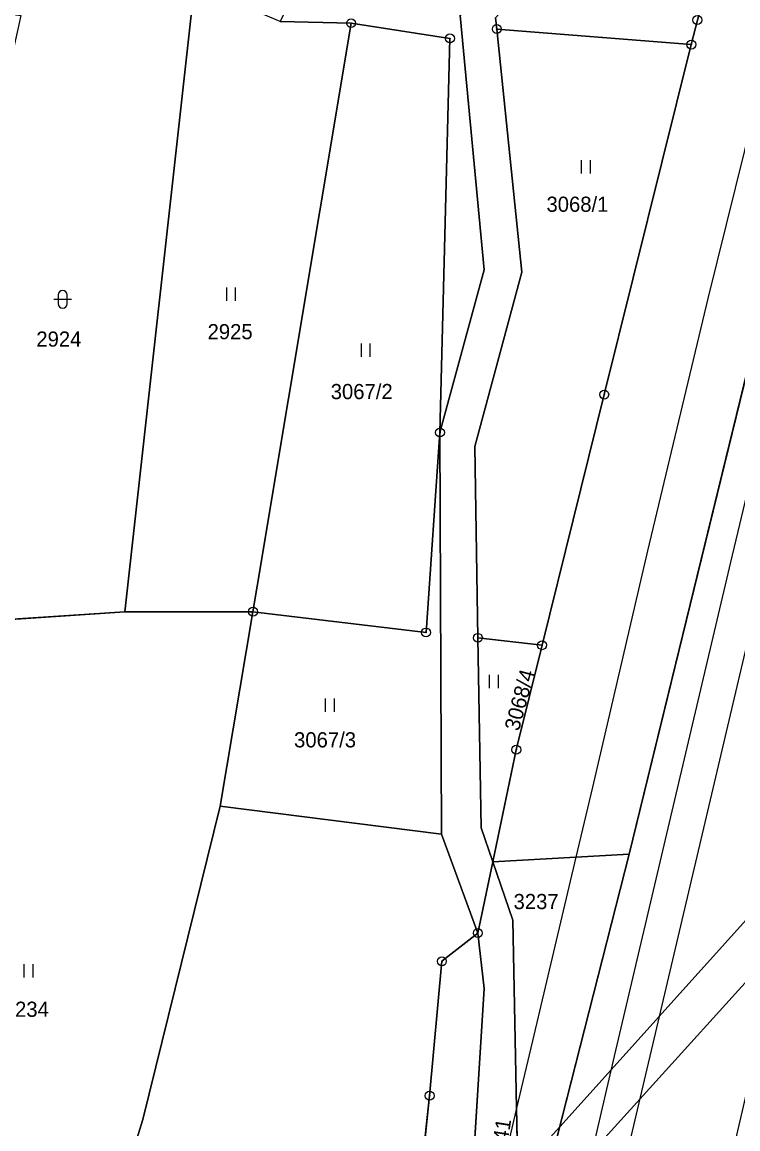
# Model space of a CAD drawing. Extents: x -689422 to -685210, y -987725 to -982160.
# Drawn here: x -686926.7 to -686846.4, y -987064.7 to -986940.6 of the extents above; entities that cross this region are included whole.
import ezdxf

# ---------------------------------------------------------------- set-up
doc = ezdxf.new("R2010")
doc.units = 0
for name, color, linetype in [('KN_Hranice_parcel', 7, 'Continuous'), ('KN_Hranice_parcel_vnitrni_kresba', 7, 'Continuous'), ('KN_Parcelni cisla', 7, 'Continuous'), ('KN_Polygon parcely', 7, 'Continuous'), ('KN_POZEMKY_OSTATNI PLOCHA', 7, 'Continuous'), ('KN_POZEMKY_TTP', 7, 'Continuous'), ('KN_POZEMKY_VODNI_PLOCHA', 7, 'Continuous'), ('KN_VYUZITI_11_vodni plocha_zamokrena plocha', 7, 'Continuous'), ('KN_VYUZITI_16_ostatni plocha_silnice', 7, 'Continuous'), ('KN_VYUZITI_27_ostatni plocha_neplodna puda', 7, 'Continuous'), ('KN_Věcná břemena k části', 7, 'Continuous'), ('KN_Značky bodu BP', 7, 'Continuous'), ('KN_Značky kultur', 7, 'Continuous')]:
    doc.layers.add(name, color=color, linetype=linetype)

msp = doc.modelspace()

# ---------------------------------------------------------------- linework, layer by layer
at = {"layer": 'KN_Hranice_parcel'}
for p, q in [((-686915.21, -987006.73), (-686907.58, -986938.09)), ((-686900.35, -987003.88), (-686889.82, -986940.72)), ((-686889.82, -986940.72), (-686897.78, -986940.52)), ((-686873.61, -986940.12), (-686873.48, -986941.38)), ((-686850.98, -986940.37), (-686851.66, -986943.12)), ((-686851.66, -986943.12), (-686873.48, -986941.38)), ((-686873.48, -986941.38), (-686870.67, -986968.64)), ((-686870.67, -986968.64), (-686875.95, -986988.19)), ((-686879.67, -987031.69), (-686879.86, -986986.63)), ((-686875.95, -986988.19), (-686875.6, -987009.66)), ((-686900.83, -987006.73), (-686900.35, -987003.88)), ((-686941.32, -987008.49), (-686915.21, -987006.73)), ((-686915.21, -987006.73), (-686900.83, -987006.73)), ((-686904.51, -987028.55), (-686900.83, -987006.73)), ((-686875.6, -987009.66), (-686875.25, -987030.98)), ((-686875.6, -987009.66), (-686868.4, -987010.49)), ((-686868.4, -987010.49), (-686871.3, -987022.21)), ((-686871.3, -987022.21), (-686873.93, -987034.78)), ((-686904.51, -987028.55), (-686879.67, -987031.69)), ((-686875.25, -987030.98), (-686873.93, -987034.78)), ((-686879.67, -987031.69), (-686875.61, -987042.77)), ((-686858.63, -987033.94), (-686876.05, -987102.29)), ((-686873.93, -987034.78), (-686875.61, -987042.77)), ((-686873.93, -987034.78), (-686871.67, -987041.32)), ((-686874.91, -987049.01), (-686875.61, -987042.77))]:
    msp.add_line(p, q, dxfattribs=at)
for points in [[(-686809.37, -986846.02), (-686821.44, -986885.64), (-686838.14, -986950.08), (-686858.63, -987033.94)], [(-686879.86, -986986.63), (-686874.89, -986968.38), (-686877.6, -986939.87), (-686859.95, -986918.72), (-686851.59, -986903.08), (-686841, -986883.31)], [(-686889.82, -986940.72), (-686878.74, -986942.43), (-686879.86, -986986.63)], [(-686851.66, -986943.12), (-686861.43, -986982.38), (-686868.4, -987010.49)], [(-686900.83, -987006.73), (-686881.42, -987009.06), (-686879.86, -986986.63)], [(-686926.56, -987106.84), (-686913.19, -987063.68), (-686904.51, -987028.55)], [(-686873.93, -987034.78), (-686864.62, -987034.27), (-686858.63, -987033.94)], [(-686871.67, -987041.32), (-686871.26, -987062.4), (-686871.04, -987073.57), (-686876.05, -987102.29)], [(-686875.61, -987042.77), (-686879.64, -987045.94), (-686881.02, -987061.02), (-686881.88, -987069.03), (-686889.8, -987097.99), (-686895.85, -987125.85)], [(-686876.05, -987102.29), (-686879.24, -987096.41), (-686879.53, -987095.87), (-686876.38, -987072.98), (-686874.91, -987049.01)]]:
    msp.add_lwpolyline(points, dxfattribs=at)
at = {"layer": 'KN_Hranice_parcel_vnitrni_kresba'}
for p, q in [((-686842.22, -986940.88), (-686849.82, -986971.61)), ((-686875.39, -987137.96), (-686832.86, -986956.93)), ((-686849.82, -986971.61), (-686856.59, -986999.9)), ((-686840.72, -986973.62), (-686847.25, -987001.16)), ((-686856.59, -986999.9), (-686862.76, -987026.4)), ((-686847.25, -987001.16), (-686853.68, -987028.46)), ((-686862.76, -987026.4), (-686864.62, -987034.27)), ((-686853.68, -987028.46), (-686860.31, -987056.58)), ((-686864.62, -987034.27), (-686869.48, -987054.85)), ((-686839.49, -987034.76), (-686861.96, -987131.65)), ((-686869.48, -987054.85), (-686871.26, -987062.4)), ((-686860.31, -987056.58), (-686866.54, -987083.15)), ((-686871.26, -987062.4), (-686875.64, -987081.01))]:
    msp.add_line(p, q, dxfattribs=at)
at = {"layer": 'KN_Polygon parcely'}
msp.add_lwpolyline([(-686747.09, -986687.93), (-686785.68, -986782.79), (-686794.86, -986807.28), (-686809.37, -986846.02), (-686821.44, -986885.64), (-686838.14, -986950.08), (-686858.63, -987033.94), (-686876.05, -987102.29)], dxfattribs=at)
for points in [[(-686815.24, -986827.16), (-686821.42, -986841.08), (-686827.34, -986859.08), (-686829.67, -986866.16), (-686840.54, -986901.19), (-686850.98, -986940.37), (-686851.66, -986943.12), (-686861.43, -986982.38), (-686868.4, -987010.49), (-686871.3, -987022.21), (-686873.93, -987034.78), (-686864.62, -987034.27), (-686858.63, -987033.94), (-686838.14, -986950.08), (-686821.44, -986885.64), (-686809.37, -986846.02), (-686794.86, -986807.28), (-686798.92, -986805.5), (-686805.65, -986802.54), (-686814.47, -986825.93), (-686813.96, -986826.56)], [(-686875.61, -987042.77), (-686873.93, -987034.78), (-686875.25, -987030.98), (-686875.6, -987009.66), (-686875.95, -986988.19), (-686870.67, -986968.64), (-686873.48, -986941.38), (-686873.61, -986940.12), (-686856.81, -986921.45), (-686848.29, -986905.16), (-686836.78, -986883.92), (-686840.43, -986873.61), (-686835.56, -986856.29), (-686839.5, -986854.96), (-686846.18, -986872.83), (-686841, -986883.31), (-686851.59, -986903.08), (-686859.95, -986918.72), (-686877.6, -986939.87), (-686874.89, -986968.38), (-686879.86, -986986.63), (-686879.67, -987031.69)], [(-686840.43, -986873.61), (-686836.78, -986883.92), (-686848.29, -986905.16), (-686856.81, -986921.45), (-686873.61, -986940.12), (-686873.48, -986941.38), (-686851.66, -986943.12), (-686850.98, -986940.37), (-686840.54, -986901.19), (-686829.67, -986866.16), (-686827.34, -986859.08), (-686835.56, -986856.29)], [(-686859.95, -986918.72), (-686851.59, -986903.08), (-686841, -986883.31), (-686861.16, -986874.49), (-686878.99, -986900.95), (-686897.78, -986940.52), (-686889.82, -986940.72), (-686878.74, -986942.43), (-686879.86, -986986.63), (-686874.89, -986968.38), (-686877.6, -986939.87)], [(-686941.32, -987008.49), (-686915.21, -987006.73), (-686907.58, -986938.09), (-686916.04, -986936.88), (-686931.42, -986936.56), (-687035.22, -986921.09), (-687034.96, -986923.61), (-686936.47, -986938.56), (-686926.88, -986939.87), (-686941.35, -987005.33), (-686948.57, -987004.84), (-686981.97, -987002.56), (-687034.11, -986992.05), (-687034.08, -986994.23), (-686980.97, -987004.74)], [(-686900.83, -987006.73), (-686900.35, -987003.88), (-686889.82, -986940.72), (-686897.78, -986940.52), (-686901.51, -986938.95), (-686907.58, -986938.09), (-686915.21, -987006.73)], [(-686879.86, -986986.63), (-686878.74, -986942.43), (-686889.82, -986940.72), (-686900.35, -987003.88), (-686900.83, -987006.73), (-686881.42, -987009.06)], [(-686873.48, -986941.38), (-686870.67, -986968.64), (-686875.95, -986988.19), (-686875.6, -987009.66), (-686868.4, -987010.49), (-686861.43, -986982.38), (-686851.66, -986943.12)], [(-686879.67, -987031.69), (-686879.86, -986986.63), (-686881.42, -987009.06), (-686900.83, -987006.73), (-686904.51, -987028.55)], [(-686904.51, -987028.55), (-686900.83, -987006.73), (-686915.21, -987006.73), (-686941.32, -987008.49), (-686941.23, -987025.06), (-686947.38, -987090.16), (-686929.71, -987120.98), (-686926.56, -987106.84), (-686913.19, -987063.68)], [(-686873.93, -987034.78), (-686871.3, -987022.21), (-686868.4, -987010.49), (-686875.6, -987009.66), (-686875.25, -987030.98)], [(-686926.56, -987106.84), (-686895.85, -987125.85), (-686889.8, -987097.99), (-686881.88, -987069.03), (-686881.02, -987061.02), (-686879.64, -987045.94), (-686875.61, -987042.77), (-686879.67, -987031.69), (-686904.51, -987028.55), (-686913.19, -987063.68)], [(-686871.04, -987073.57), (-686876.05, -987102.29), (-686858.63, -987033.94), (-686864.62, -987034.27), (-686873.93, -987034.78), (-686871.67, -987041.32), (-686871.26, -987062.4)], [(-686875.61, -987042.77), (-686874.91, -987049.01), (-686876.38, -987072.98), (-686879.53, -987095.87), (-686879.24, -987096.41), (-686876.05, -987102.29), (-686871.04, -987073.57), (-686871.26, -987062.4), (-686871.67, -987041.32), (-686873.93, -987034.78)], [(-686895.85, -987125.85), (-686887.4, -987131.07), (-686882.17, -987134.31), (-686880.68, -987119.19), (-686879.29, -987115), (-686876.05, -987102.29), (-686879.24, -987096.41), (-686879.53, -987095.87), (-686876.38, -987072.98), (-686874.91, -987049.01), (-686875.61, -987042.77), (-686879.64, -987045.94), (-686881.02, -987061.02), (-686881.88, -987069.03), (-686889.8, -987097.99)]]:
    msp.add_lwpolyline(points, close=True, dxfattribs=at)
at = {"layer": 'KN_POZEMKY_OSTATNI PLOCHA'}
for p, q in [((-686907.58, -986938.09), (-686915.21, -987006.73)), ((-686851.66, -986943.12), (-686850.98, -986940.37)), ((-686861.43, -986982.38), (-686851.66, -986943.12)), ((-686838.14, -986950.08), (-686858.63, -987033.94)), ((-686858.63, -987033.94), (-686838.14, -986950.08)), ((-686868.4, -987010.49), (-686861.43, -986982.38)), ((-686915.21, -987006.73), (-686941.32, -987008.49)), ((-686871.3, -987022.21), (-686868.4, -987010.49)), ((-686873.93, -987034.78), (-686871.3, -987022.21)), ((-686876.05, -987102.29), (-686858.63, -987033.94)), ((-686858.63, -987033.94), (-686876.05, -987102.29)), ((-686858.63, -987033.94), (-686864.62, -987034.27)), ((-686864.62, -987034.27), (-686858.63, -987033.94)), ((-686875.61, -987042.77), (-686873.93, -987034.78)), ((-686864.62, -987034.27), (-686873.93, -987034.78)), ((-686873.93, -987034.78), (-686864.62, -987034.27)), ((-686871.67, -987041.32), (-686873.93, -987034.78)), ((-686873.93, -987034.78), (-686871.67, -987041.32)), ((-686871.26, -987062.4), (-686871.67, -987041.32)), ((-686871.67, -987041.32), (-686871.26, -987062.4)), ((-686879.64, -987045.94), (-686875.61, -987042.77)), ((-686874.91, -987049.01), (-686875.61, -987042.77)), ((-686875.61, -987042.77), (-686874.91, -987049.01)), ((-686881.02, -987061.02), (-686879.64, -987045.94)), ((-686876.38, -987072.98), (-686874.91, -987049.01)), ((-686874.91, -987049.01), (-686876.38, -987072.98)), ((-686881.88, -987069.03), (-686881.02, -987061.02)), ((-686871.04, -987073.57), (-686871.26, -987062.4)), ((-686871.26, -987062.4), (-686871.04, -987073.57))]:
    msp.add_line(p, q, dxfattribs=at)
at = {"layer": 'KN_POZEMKY_TTP'}
for p, q in [((-686915.21, -987006.73), (-686907.58, -986938.09)), ((-686889.82, -986940.72), (-686900.35, -987003.88)), ((-686900.35, -987003.88), (-686889.82, -986940.72)), ((-686897.78, -986940.52), (-686889.82, -986940.72)), ((-686889.82, -986940.72), (-686897.78, -986940.52)), ((-686878.74, -986942.43), (-686889.82, -986940.72)), ((-686889.82, -986940.72), (-686878.74, -986942.43)), ((-686877.6, -986939.87), (-686874.89, -986968.38)), ((-686873.48, -986941.38), (-686873.61, -986940.12)), ((-686850.98, -986940.37), (-686851.66, -986943.12)), ((-686870.67, -986968.64), (-686873.48, -986941.38)), ((-686873.48, -986941.38), (-686851.66, -986943.12)), ((-686851.66, -986943.12), (-686873.48, -986941.38)), ((-686879.86, -986986.63), (-686878.74, -986942.43)), ((-686878.74, -986942.43), (-686879.86, -986986.63)), ((-686851.66, -986943.12), (-686861.43, -986982.38)), ((-686874.89, -986968.38), (-686879.86, -986986.63)), ((-686875.95, -986988.19), (-686870.67, -986968.64)), ((-686861.43, -986982.38), (-686868.4, -987010.49)), ((-686879.86, -986986.63), (-686881.42, -987009.06)), ((-686881.42, -987009.06), (-686879.86, -986986.63)), ((-686879.86, -986986.63), (-686879.67, -987031.69)), ((-686875.6, -987009.66), (-686875.95, -986988.19)), ((-686900.35, -987003.88), (-686900.83, -987006.73)), ((-686900.83, -987006.73), (-686900.35, -987003.88)), ((-686941.32, -987008.49), (-686915.21, -987006.73)), ((-686900.83, -987006.73), (-686915.21, -987006.73)), ((-686915.21, -987006.73), (-686900.83, -987006.73)), ((-686900.83, -987006.73), (-686904.51, -987028.55)), ((-686904.51, -987028.55), (-686900.83, -987006.73)), ((-686881.42, -987009.06), (-686900.83, -987006.73)), ((-686900.83, -987006.73), (-686881.42, -987009.06)), ((-686868.4, -987010.49), (-686875.6, -987009.66)), ((-686875.6, -987009.66), (-686868.4, -987010.49)), ((-686875.25, -987030.98), (-686875.6, -987009.66)), ((-686868.4, -987010.49), (-686871.3, -987022.21)), ((-686871.3, -987022.21), (-686873.93, -987034.78)), ((-686904.51, -987028.55), (-686913.19, -987063.68)), ((-686913.19, -987063.68), (-686904.51, -987028.55)), ((-686904.51, -987028.55), (-686879.67, -987031.69)), ((-686879.67, -987031.69), (-686904.51, -987028.55)), ((-686873.93, -987034.78), (-686875.25, -987030.98)), ((-686879.67, -987031.69), (-686875.61, -987042.77)), ((-686875.61, -987042.77), (-686879.64, -987045.94)), ((-686879.64, -987045.94), (-686881.02, -987061.02)), ((-686881.02, -987061.02), (-686881.88, -987069.03)), ((-686913.19, -987063.68), (-686926.56, -987106.84)), ((-686926.56, -987106.84), (-686913.19, -987063.68))]:
    msp.add_line(p, q, dxfattribs=at)
at = {"layer": 'KN_POZEMKY_VODNI_PLOCHA'}
for p, q in [((-686874.89, -986968.38), (-686877.6, -986939.87)), ((-686873.61, -986940.12), (-686873.48, -986941.38)), ((-686873.48, -986941.38), (-686870.67, -986968.64)), ((-686879.86, -986986.63), (-686874.89, -986968.38)), ((-686870.67, -986968.64), (-686875.95, -986988.19)), ((-686879.67, -987031.69), (-686879.86, -986986.63)), ((-686875.95, -986988.19), (-686875.6, -987009.66)), ((-686875.6, -987009.66), (-686875.25, -987030.98)), ((-686875.25, -987030.98), (-686873.93, -987034.78)), ((-686875.61, -987042.77), (-686879.67, -987031.69)), ((-686873.93, -987034.78), (-686875.61, -987042.77))]:
    msp.add_line(p, q, dxfattribs=at)
at = {"layer": 'KN_VYUZITI_11_vodni plocha_zamokrena plocha'}
for p, q in [((-686874.89, -986968.38), (-686877.6, -986939.87)), ((-686873.61, -986940.12), (-686873.48, -986941.38)), ((-686873.48, -986941.38), (-686870.67, -986968.64)), ((-686879.86, -986986.63), (-686874.89, -986968.38)), ((-686870.67, -986968.64), (-686875.95, -986988.19)), ((-686879.67, -987031.69), (-686879.86, -986986.63)), ((-686875.95, -986988.19), (-686875.6, -987009.66)), ((-686875.6, -987009.66), (-686875.25, -987030.98)), ((-686875.25, -987030.98), (-686873.93, -987034.78)), ((-686875.61, -987042.77), (-686879.67, -987031.69)), ((-686873.93, -987034.78), (-686875.61, -987042.77))]:
    msp.add_line(p, q, dxfattribs=at)
at = {"layer": 'KN_VYUZITI_16_ostatni plocha_silnice'}
for p, q in [((-686851.66, -986943.12), (-686850.98, -986940.37)), ((-686861.43, -986982.38), (-686851.66, -986943.12)), ((-686838.14, -986950.08), (-686858.63, -987033.94)), ((-686858.63, -987033.94), (-686838.14, -986950.08)), ((-686868.4, -987010.49), (-686861.43, -986982.38)), ((-686871.3, -987022.21), (-686868.4, -987010.49)), ((-686873.93, -987034.78), (-686871.3, -987022.21)), ((-686876.05, -987102.29), (-686858.63, -987033.94)), ((-686858.63, -987033.94), (-686876.05, -987102.29)), ((-686858.63, -987033.94), (-686864.62, -987034.27)), ((-686864.62, -987034.27), (-686858.63, -987033.94)), ((-686875.61, -987042.77), (-686873.93, -987034.78)), ((-686864.62, -987034.27), (-686873.93, -987034.78)), ((-686873.93, -987034.78), (-686864.62, -987034.27)), ((-686871.67, -987041.32), (-686873.93, -987034.78)), ((-686873.93, -987034.78), (-686871.67, -987041.32)), ((-686871.26, -987062.4), (-686871.67, -987041.32)), ((-686871.67, -987041.32), (-686871.26, -987062.4)), ((-686879.64, -987045.94), (-686875.61, -987042.77)), ((-686874.91, -987049.01), (-686875.61, -987042.77)), ((-686875.61, -987042.77), (-686874.91, -987049.01)), ((-686881.02, -987061.02), (-686879.64, -987045.94)), ((-686876.38, -987072.98), (-686874.91, -987049.01)), ((-686874.91, -987049.01), (-686876.38, -987072.98)), ((-686881.88, -987069.03), (-686881.02, -987061.02)), ((-686871.04, -987073.57), (-686871.26, -987062.4)), ((-686871.26, -987062.4), (-686871.04, -987073.57))]:
    msp.add_line(p, q, dxfattribs=at)
at = {"layer": 'KN_VYUZITI_27_ostatni plocha_neplodna puda'}
for p, q in [((-686907.58, -986938.09), (-686915.21, -987006.73)), ((-686915.21, -987006.73), (-686941.32, -987008.49))]:
    msp.add_line(p, q, dxfattribs=at)
at = {"layer": 'KN_Věcná břemena k části'}
msp.add_lwpolyline([(-686871.12, -987069.7), (-686871.04, -987073.57), (-686871.66, -987077.13), (-686868.84, -987074.02), (-686832.08, -987033.41), (-686831.93, -987033.05), (-686831.23, -987029.88), (-686833.36, -987027.8), (-686866.42, -987064.49)], close=True, dxfattribs=at)
at = {"layer": 'KN_Značky bodu BP'}
for centre, radius in [((-686889.82, -986940.72), 0.5), ((-686889.82, -986940.72), 0.0303), ((-686873.48, -986941.38), 0.5), ((-686850.98, -986940.37), 0.5), ((-686878.74, -986942.43), 0.5), ((-686873.48, -986941.38), 0.0303), ((-686878.74, -986942.43), 0.0303), ((-686851.66, -986943.12), 0.5), ((-686851.66, -986943.12), 0.0303), ((-686861.43, -986982.38), 0.5), ((-686861.43, -986982.38), 0.0303), ((-686879.86, -986986.63), 0.5), ((-686879.86, -986986.63), 0.0303), ((-686900.83, -987006.73), 0.5), ((-686900.83, -987006.73), 0.0303), ((-686881.42, -987009.06), 0.5), ((-686881.42, -987009.06), 0.0303), ((-686875.6, -987009.66), 0.5), ((-686875.6, -987009.66), 0.0303), ((-686868.4, -987010.49), 0.5), ((-686868.4, -987010.49), 0.0303), ((-686871.3, -987022.21), 0.5), ((-686871.3, -987022.21), 0.0303), ((-686875.61, -987042.77), 0.5), ((-686875.61, -987042.77), 0.0303), ((-686879.64, -987045.94), 0.5), ((-686879.64, -987045.94), 0.0303), ((-686881.02, -987061.02), 0.5), ((-686881.02, -987061.02), 0.0303)]:
    msp.add_circle(centre, radius, dxfattribs=at)
at = {"layer": 'KN_Značky kultur'}
for p, q in [((-686863.97, -986957.58), (-686863.97, -986956.08)), ((-686862.97, -986957.58), (-686862.97, -986956.08)), ((-686903.77, -986971.85), (-686903.77, -986970.35)), ((-686902.77, -986971.85), (-686902.77, -986970.35)), ((-686923.18, -986971.69), (-686921.18, -986971.69)), ((-686922.68, -986971.19), (-686922.68, -986972.19)), ((-686921.68, -986972.19), (-686921.68, -986971.19)), ((-686888.67, -986978.14), (-686888.67, -986976.64)), ((-686887.67, -986978.14), (-686887.67, -986976.64)), ((-686874.28, -987015.32), (-686874.28, -987013.82)), ((-686873.28, -987015.32), (-686873.28, -987013.82)), ((-686892.7, -987017.96), (-686892.7, -987016.46)), ((-686891.7, -987017.96), (-686891.7, -987016.46)), ((-686926.5, -987047.77), (-686926.5, -987046.27)), ((-686925.5, -987047.77), (-686925.5, -987046.27))]:
    msp.add_line(p, q, dxfattribs=at)
for centre, start, end in [((-686922.18, -986971.19), 0, 180), ((-686922.18, -986972.19), 180, 359.9879)]:
    msp.add_arc(centre, 0.5, start, end, dxfattribs=at)

# ---------------------------------------------------------------- texts
at = {"layer": 'KN_Parcelni cisla'}
for s, p in [('3068/1', (-686867.91, -986961.88)), ('2925', (-686905.92, -986976.17)), ('2924', (-686925.13, -986977)), ('3067/2', (-686892.11, -986982.89)), ('3067/3', (-686896.22, -987021.95)), ('3237', (-686871.6, -987040.09)), ('3234', (-686928.78, -987052.17))]:
    msp.add_text(s, height=1.7, dxfattribs=at).set_placement(p)
for s, rotation, p in [('3068/4', 75, (-686871, -987020.2)), ('3241', 81, (-686872.64, -987068.73))]:
    msp.add_text(s, height=1.7, rotation=rotation, dxfattribs=at).set_placement(p)

doc.saveas('drawing.dxf')
